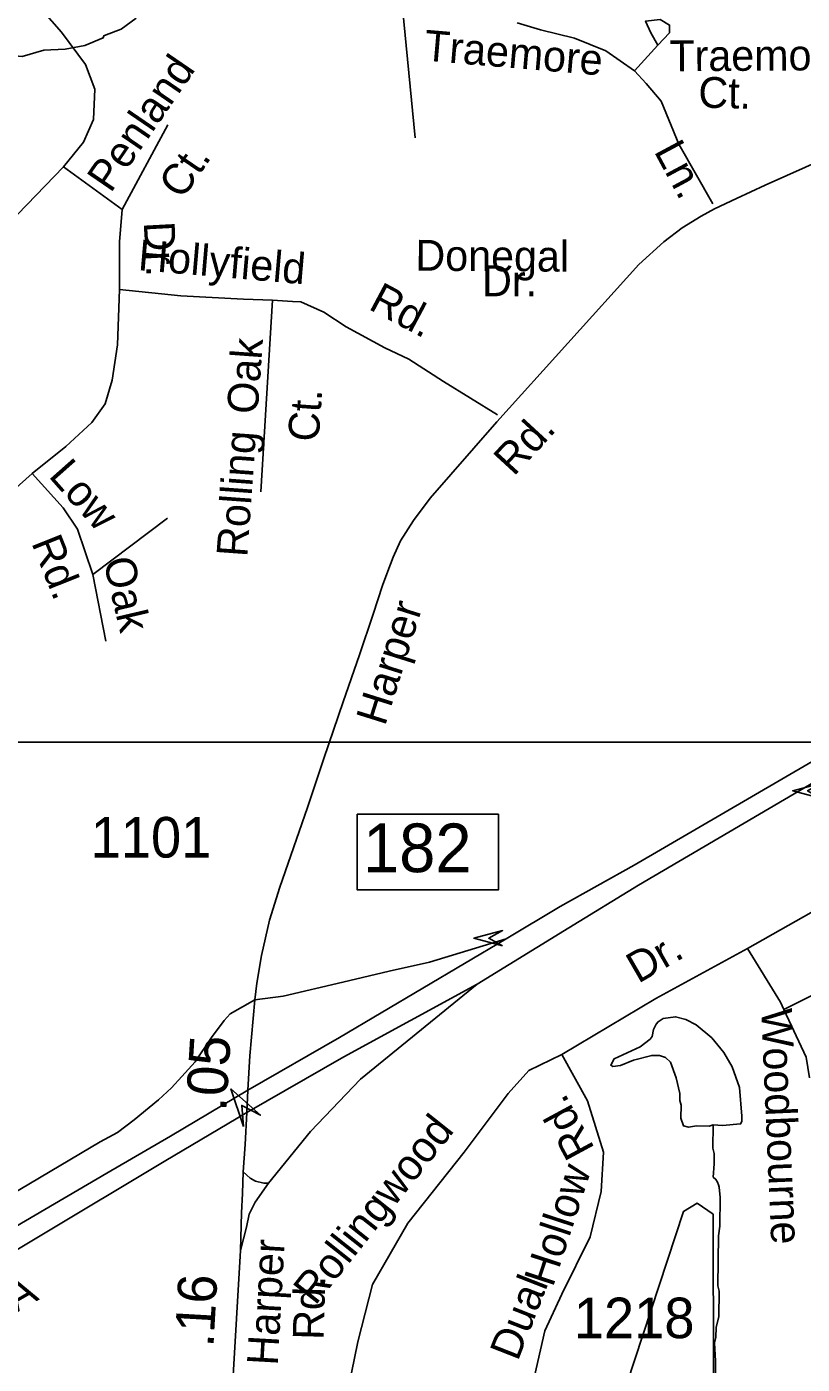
# Model space of a CAD drawing. Extents: x 1547597 to 1699558, y 810033 to 920809.
# Drawn here: x 1583848 to 1586237, y 829390 to 833512 of the extents above; entities that cross this region are included whole.
import ezdxf

# ---------------------------------------------------------------- set-up
doc = ezdxf.new("R2010")
doc.units = 0
for name, color, linetype in [('Exist Hydrographic Misc Water Feature', 7, 'Continuous'), ('Exist Hydrographic Pond Under 1500 Sq Ft', 7, 'Continuous'), ('Exist Road Non-System Type 51', 7, 'Continuous'), ('Exist Road Non-System Type 51 Label', 7, 'Continuous'), ('Exist Road Primary Interstate Divided Center Attributed', 7, 'Continuous'), ('Exist Road Primary Interstate Interchange CELL', 7, 'Continuous'), ('Exist Road Primary Interstate Label', 7, 'Continuous'), ('Exist Road Primary Interstate Ramp 1 Lane Attributed', 7, 'Continuous'), ('Exist Road Primary Interstate Structure Cantilever Sign Attributed CELL', 7, 'Continuous'), ('Exist Road Primary Interstate Structure Ovrhead Sign Attributed CELL', 7, 'Continuous'), ('Exist Road Secondary Mileage Hundredths English Label', 7, 'Continuous'), ('Exist Road Secondary Structure Standard Bridge Attributed CELL', 7, 'Continuous'), ('Exist Road Secondary Type 51 Attributed', 7, 'Continuous'), ('Exist Road Secondary Type 51 Label', 7, 'Continuous'), ('Exist Road Secondary Type 51 Number Label', 7, 'Continuous'), ('Map Preparation Inset Cut Line', 7, 'Continuous')]:
    doc.layers.add(name, color=color, linetype=linetype)

msp = doc.modelspace()

# ---------------------------------------------------------------- linework, layer by layer
at = {"layer": 'Exist Hydrographic Misc Water Feature'}
for points in [[(1584185.3, 833538.7), (1584139, 833505.2), (1584092.8, 833487.9), (1584084.8, 833484), (1584082.7, 833478), (1584026.4, 833454.7), (1583966.2, 833443.5), (1583900.3, 833440.6), (1583834.1, 833421.1), (1583778.1, 833425.8), (1583650.6, 833459.4)], [(1585962.5, 830128.4), (1585950.4, 830124), (1585910.4, 830124.5), (1585886.4, 830120.8), (1585870.5, 830125), (1585862.8, 830149.1), (1585863.3, 830189.1), (1585859.4, 830203.1), (1585859.7, 830225.1), (1585848.3, 830273.3), (1585830.9, 830321.5), (1585815, 830335.7), (1585797, 830341.9), (1585773.1, 830342.2), (1585717, 830326.9), (1585676.8, 830311.4), (1585652.7, 830307.7), (1585646.7, 830311.8), (1585657, 830331.6), (1585737.4, 830368.6), (1585767.7, 830392.2), (1585773.8, 830400.1), (1585778.1, 830422), (1585786.2, 830437.9), (1585792.3, 830445.9), (1585808.4, 830455.7), (1585846.5, 830461.2), (1585878.3, 830452.8), (1585910.1, 830436.4), (1585957.7, 830395.8), (1585995.1, 830351.3), (1586020.7, 830307), (1586043.8, 830242.8), (1586050.8, 830154.7), (1586050.6, 830138.7), (1586046.5, 830130.8), (1585990.5, 830125.5), (1585962.5, 830128.4)], [(1585962.5, 830128.4), (1585961.7, 830055.9), (1585965.5, 830039.9), (1585965.1, 830007.9), (1585962.4, 829966.7)], [(1585962.4, 829966.7), (1585970.8, 829960), (1585975.7, 829951.7), (1585978.8, 829943.5), (1585980.3, 829935.7), (1585983.8, 829903.7), (1585982.8, 829815.7), (1585978.4, 829785.8), (1585976.7, 829631.9), (1585980.5, 829615.9), (1585979.4, 829535.9), (1585971.1, 829504.1), (1585970.7, 829472.1), (1585966.5, 829456.1), (1585969.9, 829400.1), (1585968.7, 829296.2)]]:
    msp.add_lwpolyline(points, dxfattribs=at)
at = {"layer": 'Exist Hydrographic Pond Under 1500 Sq Ft'}
msp.add_lwpolyline([(1585787.5, 829294.9), (1585696.6, 829329.5), (1585870.6, 829861.1), (1585912.6, 829886.4), (1585962.5, 829852.6), (1585963.5, 829350.4), (1585920.6, 829292.1), (1585787.5, 829294.9)], dxfattribs=at)
at = {"layer": 'Exist Road Non-System Type 51'}
msp.add_line((1584604.4, 832669.7), (1584569.3, 832079.3), dxfattribs=at)
for points in [[(1583961.4, 833080.2), (1584022.6, 833156.3), (1584053.2, 833226.8), (1584057.8, 833320.4), (1584028.7, 833395.6), (1583955.1, 833495.3), (1583872.4, 833589.5), (1583824.9, 833672.4), (1583814.2, 833729.1), (1583812.1, 833811.6)], [(1585005.4, 833570.6), (1585043.8, 833169.7)], [(1585792.2, 833455.4), (1585828.2, 833493.8), (1585828.2, 833517.8), (1585799.4, 833534.6), (1585753.8, 833529.8), (1585770.6, 833493.8), (1585792.2, 833455.4)], [(1585720.2, 833376.2), (1585631.5, 833438.6), (1585535.5, 833477), (1585430, 833503.4), (1585358, 833525)], [(1585720.2, 833376.2), (1585792.2, 833455.4)], [(1585961.7, 832967.1), (1585856.9, 833150.5), (1585801.8, 833282.6), (1585756.2, 833337.8), (1585720.2, 833376.2)], [(1584141.5, 832949.6), (1584282.5, 833210.4)], [(1583745.3, 832843.9), (1583791.2, 832905.3), (1583961.4, 833080.2)], [(1583961.4, 833080.2), (1584141.5, 832949.6)], [(1584141.5, 832949.6), (1584133.9, 832849.9), (1584133.9, 832702.6)], [(1584133.9, 832702.6), (1584127.8, 832531.6), (1584110.9, 832422.7), (1584089.4, 832350.6), (1584048.1, 832292.3), (1583968.3, 832218.7), (1583864.1, 832135.9)], [(1584133.9, 832702.6), (1584322.4, 832683.5), (1584515.5, 832672.8), (1584604.4, 832669.7)], [(1585297.9, 832316.3), (1585131.6, 832419.4), (1585024.9, 832488.2), (1584950.8, 832522.6), (1584831.4, 832587.7), (1584762.7, 832632.9), (1584692, 832664.4), (1584666.9, 832665.5), (1584604.4, 832669.7)], [(1583864.1, 832135.9), (1583657.9, 831951.6), (1583565.9, 831861.1), (1583477, 831759.9), (1583296.1, 831565.1)], [(1583864.1, 832135.9), (1583959.8, 832029.9), (1584004.3, 831963.9), (1584051.8, 831824.3)], [(1584051.8, 831824.3), (1584281.7, 831997.6)], [(1584051.8, 831824.3), (1584091.7, 831618.8)], [(1586068, 830671.9), (1586467.3, 830898)], [(1585496.3, 830345), (1585785.5, 830517.3), (1586068, 830671.9)], [(1586068, 830671.9), (1586169.7, 830506), (1586180.3, 830483.3)], [(1586180.3, 830483.3), (1586361.8, 830573.8)], [(1586180.3, 830483.3), (1586248.8, 830336.4), (1586259.3, 830273.4)], [(1584838.9, 829318.1), (1584867.3, 829459.2), (1584912.5, 829636.3), (1585021.7, 829824.8), (1585194.9, 830043.4), (1585330.5, 830224.4), (1585394.6, 830296), (1585496.3, 830345)], [(1585496.3, 830345), (1585575.4, 830201.8), (1585624.3, 830043.4), (1585616.8, 829922.8), (1585582.9, 829783.3), (1585496.3, 829606.2), (1585443.5, 829493.1), (1585417.2, 829376.2), (1585394.6, 829274.5)]]:
    msp.add_lwpolyline(points, dxfattribs=at)
at = {"layer": 'Exist Road Primary Interstate Divided Center Attributed'}
for points in [[(1589848.5, 833751.3), (1589658.6, 833580.5), (1589540.3, 833466.4), (1589356.3, 833290.3), (1589142.9, 833117), (1588986.4, 832984.1), (1588827.6, 832856), (1588637.9, 832716), (1588488.1, 832602), (1588294.6, 832463.1), (1588074.6, 832323), (1587900.8, 832204.6), (1587557, 832002.9), (1586266.8, 831248.2), (1585718.9, 830928), (1585491, 830800.8), (1585324.1, 830701.8)], [(1585234.9, 830561.5), (1585517.3, 830735), (1585731.8, 830866.8), (1586987.1, 831603), (1587587.3, 831940.1), (1587859, 832098.4), (1588070.6, 832232.4), (1588244.8, 832347.1), (1588508.9, 832531.4), (1588679, 832655.3), (1588913.3, 832831.3), (1589044.6, 832935.3), (1589274.4, 833125.4), (1589476.9, 833298.9), (1589624.3, 833431.2), (1589802.5, 833600.6), (1589823.8, 833616.2)], [(1585324.1, 830701.8), (1584810.7, 830397.3), (1584528.8, 830234.7)], [(1584525.9, 830165.7), (1584824.9, 830337.9), (1585234.9, 830561.5)], [(1584528.8, 830234.7), (1584290.7, 830093.3), (1584094.5, 829978.6), (1583401.4, 829573.8), (1581098.9, 828235.9), (1580507.2, 827883.1)], [(1580539.7, 827829.7), (1581661.5, 828482.9), (1583505.8, 829557.3), (1584270.9, 830014.6), (1584525.9, 830165.7)]]:
    msp.add_lwpolyline(points, dxfattribs=at)
at = {"layer": 'Exist Road Primary Interstate Interchange CELL'}
msp.add_lwpolyline([(1584865.8, 831085.2), (1585300.8, 831085.2), (1585300.8, 830852), (1584865.8, 830852)], close=True, dxfattribs=at)
at = {"layer": 'Exist Road Primary Interstate Ramp 1 Lane Attributed'}
for points in [[(1585324.1, 830701.8), (1585088.8, 830629.6), (1584964.2, 830601.6), (1584821.8, 830567.6), (1584637.7, 830524.8), (1584550.3, 830513.1)], [(1584592, 829947.8), (1584722, 830107.3), (1584875.9, 830268.6), (1585234.9, 830561.5)], [(1584514.9, 829983.5), (1584536.2, 829963.4), (1584552.1, 829954), (1584578, 829948.7), (1584592, 829947.8)], [(1584506.7, 829740.5), (1584524.4, 829812.4), (1584532.6, 829852.5), (1584550.9, 829889.7), (1584592, 829947.8)]]:
    msp.add_lwpolyline(points, dxfattribs=at)
at = {"layer": 'Exist Road Primary Interstate Structure Cantilever Sign Attributed CELL'}
msp.add_lwpolyline([(1586295.7, 831134), (1586207.4, 831157.7), (1586295.7, 831181.3), (1586253.1, 831157.7)], close=True, dxfattribs=at)
at = {"layer": 'Exist Road Primary Interstate Structure Ovrhead Sign Attributed CELL'}
msp.add_lwpolyline([(1585313.3, 830679.4), (1585225, 830703.1), (1585313.3, 830726.8), (1585270.7, 830703.1)], close=True, dxfattribs=at)
at = {"layer": 'Exist Road Secondary Structure Standard Bridge Attributed CELL'}
msp.add_lwpolyline([(1584515, 830123), (1584476.9, 830238.8), (1584567.8, 830157.6), (1584510.3, 830187.8)], close=True, dxfattribs=at)
at = {"layer": 'Exist Road Secondary Type 51 Attributed'}
for points in [[(1586504.5, 833194.4), (1586122, 833023.7), (1586034.2, 832983.6), (1585966.3, 832951.2), (1585925.4, 832928.7), (1585866.4, 832892.2), (1585809.8, 832849.7), (1585733.7, 832779.5), (1585295.8, 832294.7), (1585153.7, 832132.6), (1585090, 832059.4), (1585039.2, 831991), (1584999.1, 831928.5), (1584976.1, 831877.8), (1584960.2, 831834.1), (1584943.7, 831790.5), (1584914.8, 831702), (1584872.3, 831576.4), (1584822.2, 831431.9), (1584763.2, 831257.4), (1584713.1, 831106.4), (1584627.6, 830861), (1584596, 830758.4), (1584571.3, 830650), (1584556.2, 830565), (1584550.3, 830513.1)], [(1584550.3, 830513.1), (1584474, 830470), (1584456.3, 830449.4), (1584417.3, 830396.9), (1584366.6, 830322.6), (1584325.1, 830276.7), (1584293.9, 830241.9), (1584253.7, 830205.3), (1584224.4, 830181.4), (1584178.6, 830143), (1584127.3, 830104.5), (1584074.2, 830075.2), (1583638.9, 829817.8)], [(1584550.3, 830513.1), (1584535.3, 830340.3), (1584528.8, 830234.7)], [(1584528.8, 830234.7), (1584525.9, 830165.7)], [(1584525.9, 830165.7), (1584520.5, 830067.8), (1584514.9, 829983.5)], [(1584514.9, 829983.5), (1584512, 829916.8), (1584509.6, 829857.3), (1584506.7, 829740.5)], [(1584506.7, 829740.5), (1584481.9, 829321)]]:
    msp.add_lwpolyline(points, dxfattribs=at)
at = {"layer": 'Map Preparation Inset Cut Line'}
for points in [[(1633724, 874749.3), (1571208, 874749.3), (1571208, 831307.2), (1633724, 831307.2)], [(1575502.6, 831307.2), (1641328.6, 831307.2), (1641328.6, 811336.3), (1575502.6, 811336.3)]]:
    msp.add_lwpolyline(points, close=True, dxfattribs=at)

# ---------------------------------------------------------------- texts
at = {"layer": 'Exist Road Non-System Type 51 Label'}
for s, rotation, p in [('Traemore', 355.1788, (1585069.4, 833408.5)), ('Traemore', 0.3944, (1585827.7, 833375.1)), ('Penland', 55.5966, (1584106.3, 832997.4)), ('Ct.', 358.749, (1585915.9, 833263.3)), ('Ln.', 298.2549, (1585778.4, 833129.1)), ('Ct.', 55.5966, (1584326.9, 832977.1)), ('Dr.', 273.0629, (1584207.9, 832909.8)), ('Hollyfield', 355.1141, (1584188.7, 832762.6)), ('Donegal', 359.5857, (1585044.8, 832760.8)), ('Dr.', 359.9748, (1585250.4, 832681.9)), ('Rd.', 331.9868, (1584897.3, 832643.9)), ('Oak', 85.8448, (1584558.7, 832316.7)), ('Ct.', 85.8448, (1584746.5, 832231.5)), ('Rolling', 85.8448, (1584526.8, 831876.4)), ('Low', 311.5308, (1583912.5, 832127)), ('Rd.', 291.7497, (1583861.2, 831922.3)), ('Oak', 283.1927, (1584083.1, 831867.2)), ('Dr.', 29.9645, (1585731.2, 830562.2)), ('Woodbourne', 272.4788, (1586110, 830484.7)), ('Rd.', 118.4277, (1585598.6, 830054.9)), ('Rollingwood', 51.4954, (1584736.4, 829568.7)), ('Hollow', 71.8936, (1585468.4, 829625.1)), ('Dual', 68.5963, (1585360.1, 829397.1))]:
    msp.add_text(s, height=95, rotation=rotation, dxfattribs=at).set_placement(p)
at = {"layer": 'Exist Road Primary Interstate Interchange CELL'}
msp.add_text('182', height=150, dxfattribs=at).set_placement((1584883.4, 830906.8))
at = {"layer": 'Exist Road Primary Interstate Label'}
msp.add_text('FCA', height=95, rotation=30.1236, dxfattribs=at).set_placement((1583669, 829463.1))
at = {"layer": 'Exist Road Secondary Mileage Hundredths English Label'}
for s, height, rotation, p in [('.05', 125, 86.4835, (1584462, 830167.4)), ('.16', 120, 86.7797, (1584422.7, 829441))]:
    msp.add_text(s, height=height, rotation=rotation, dxfattribs=at).set_placement(p)
at = {"layer": 'Exist Road Secondary Type 51 Label'}
for s, rotation, p in [('Rd.', 47.3469, (1585347.9, 832124.4)), ('Harper', 72.5453, (1584951.3, 831354.6)), ('Harper', 86.7797, (1584620.7, 829384.9)), ('Rd.', 88.3923, (1584762, 829464.4))]:
    msp.add_text(s, height=95, rotation=rotation, dxfattribs=at).set_placement(p)
at = {"layer": 'Exist Road Secondary Type 51 Number Label'}
for s, p in [('1101', (1584044.6, 830951.8)), ('1218', (1585532.9, 829470.5))]:
    msp.add_text(s, height=125, dxfattribs=at).set_placement(p)

doc.saveas('drawing.dxf')
